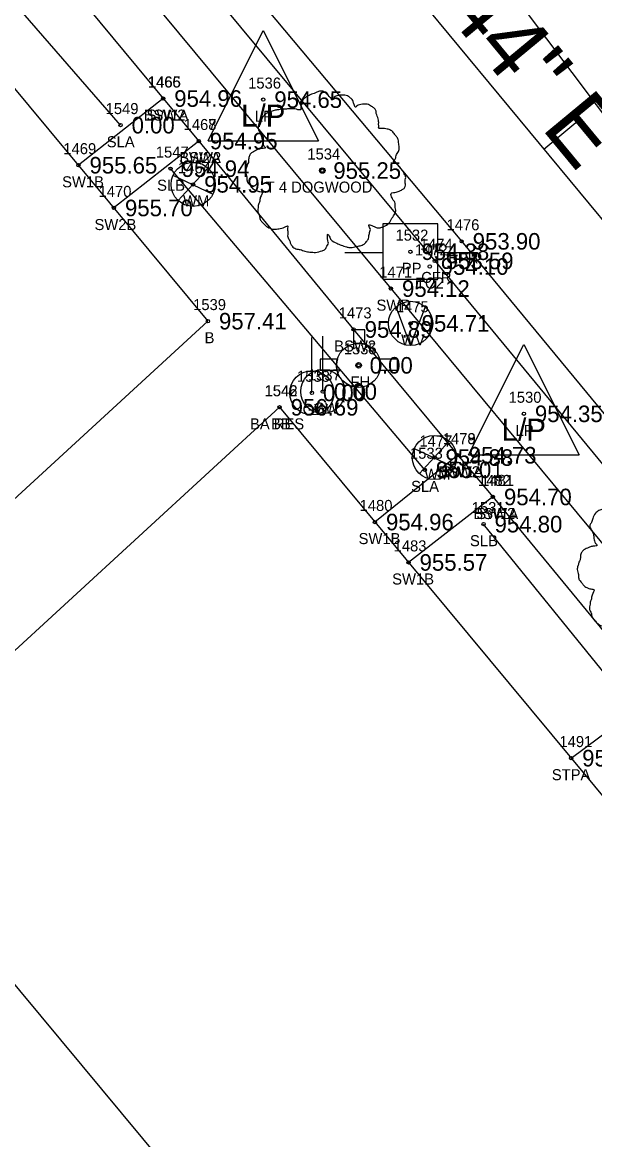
# Model space of a CAD drawing. Extents: x 1575382 to 1578175, y 1099175 to 1101955.
# Drawn here: x 1576458 to 1576509.8, y 1099400.6 to 1099501.7 of the extents above; entities that cross this region are included whole.
import ezdxf

# ---------------------------------------------------------------- set-up
doc = ezdxf.new("R2010")
doc.units = 0
for name, color, linetype in [('RD_EX_Bldg', 7, 'Continuous'), ('RD_EX_Bldg_txCode', 7, 'Continuous'), ('RD_EX_Conc', 7, 'Continuous'), ('RD_EX_Conc_txCode', 7, 'Continuous'), ('RD_EX_Road', 7, 'Continuous'), ('RD_EX_Road_txCode', 7, 'Continuous'), ('RD_EX_TX_Bldg_ELEV', 7, 'Continuous'), ('RD_EX_TX_Conc_ELEV', 7, 'Continuous'), ('RD_EX_TX_Road_ELEV', 7, 'Continuous'), ('RD_EX_TX_UT_ELEV', 7, 'Continuous'), ('RD_EX_TX_VEG_ELEV', 7, 'Continuous'), ('RD_EX_UT', 7, 'Continuous'), ('RD_EX_UT_txCode', 7, 'Continuous'), ('RD_EX_VEG', 7, 'Continuous'), ('RD_EX_VEG_txCode', 7, 'Continuous'), ('RD_HC_Cl', 7, 'Continuous'), ('RD_HC_Data', 7, 'Continuous'), ('RD_HC_Data_Tic', 7, 'Continuous'), ('RD_HC_Survey_ELEV', 7, 'Continuous'), ('RD_SMD_Locator', 7, 'Continuous')]:
    doc.layers.add(name, color=color, linetype=linetype)

msp = doc.modelspace()

# ---------------------------------------------------------------- linework, layer by layer
at = {"layer": 'RD_EX_Bldg'}
for points in [[(1576370.24, 1099519.44), (1576408.46, 1099554.56), (1576474.83, 1099474.68), (1576436.61, 1099439.56), (1576370.24, 1099519.44)], [(1576481.32, 1099466.88), (1576547.69, 1099387), (1576509.46, 1099351.88), (1576443.09, 1099431.76), (1576481.32, 1099466.88)]]:
    msp.add_lwpolyline(points, dxfattribs=at)
at = {"layer": 'RD_EX_Conc'}
for p, q in [((1576470.78, 1099494.84), (1576463.11, 1099488.8)), ((1576474, 1099490.99), (1576466.32, 1099484.93)), ((1576497.44, 1099462.54), (1576489.95, 1099456.49)), ((1576500.63, 1099458.76), (1576492.99, 1099452.83))]:
    msp.add_line(p, q, dxfattribs=at)
for points in [[(1576396.55, 1099574.21), (1576400.94, 1099578.26), (1576405.4, 1099581.45), (1576408.35, 1099582.39), (1576411.1, 1099581.54), (1576412.48, 1099580.16), (1576412.48, 1099580.16), (1576431.43, 1099557.37), (1576462.58, 1099519.63), (1576495.36, 1099480.14), (1576526.3, 1099442.62), (1576558.03, 1099404.43)], [(1576424.53, 1099564.75), (1576421.54, 1099562.11), (1576427.77, 1099554.24), (1576491.4, 1099477.63), (1576522.92, 1099439.59), (1576554.46, 1099401.18)], [(1576417.79, 1099558.83), (1576419.81, 1099556.41), (1576422.78, 1099552.79), (1576443.67, 1099527.67), (1576447.39, 1099523.04), (1576450.38, 1099519.36), (1576454.58, 1099514.36), (1576470.78, 1099494.84), (1576474, 1099490.99), (1576488.02, 1099473.93), (1576497.44, 1099462.54), (1576500.63, 1099458.76), (1576516.67, 1099439.27), (1576520.69, 1099434.46), (1576523.68, 1099430.77), (1576527.93, 1099425.88), (1576541.66, 1099409.22), (1576544.52, 1099405.7), (1576551.21, 1099397.69)], [(1576507.71, 1099435.11), (1576511.48, 1099437.92), (1576525.28, 1099420.93), (1576521.71, 1099418.27)]]:
    msp.add_lwpolyline(points, dxfattribs=at)
at = {"layer": 'RD_EX_Road'}
msp.add_lwpolyline([(1576365.09, 1099547.1), (1576400.46, 1099578.87), (1576404.99, 1099582.28), (1576408.27, 1099583.27), (1576411.47, 1099582.29), (1576413.12, 1099580.85), (1576414.82, 1099582.11), (1576433.7, 1099559), (1576464.95, 1099521.11), (1576497.8, 1099481.91), (1576528.73, 1099444.46), (1576560.01, 1099406.61)], dxfattribs=at)
at = {"layer": 'RD_EX_UT'}
for p, q in [((1576474.84, 1099491.01), (1576479.84, 1099501.01)), ((1576479.84, 1099501.01), (1576484.84, 1099491.01)), ((1576474.84, 1099491.01), (1576484.84, 1099491.01)), ((1576472.14, 1099485.61), (1576474.8, 1099488.51)), ((1576471.65, 1099487.91), (1576475.28, 1099486.19)), ((1576495.65, 1099483.48), (1576490.65, 1099483.48)), ((1576490.65, 1099483.48), (1576490.65, 1099478.48)), ((1576495.65, 1099478.48), (1576495.65, 1099483.48)), ((1576487.22, 1099480.91), (1576490.69, 1099480.91)), ((1576495.58, 1099480.91), (1576499.22, 1099480.91)), ((1576490.65, 1099478.48), (1576495.65, 1099478.48)), ((1576493.18, 1099472.49), (1576491.88, 1099475.97)), ((1576493.18, 1099472.49), (1576494.5, 1099475.93)), ((1576488.02, 1099473.9), (1576488.02, 1099472.62)), ((1576489.02, 1099473.9), (1576488.02, 1099473.9)), ((1576489.02, 1099472.6), (1576489.02, 1099473.9)), ((1576484.24, 1099468.19), (1576484.24, 1099473.19)), ((1576485.23, 1099468.31), (1576485.23, 1099473.31)), ((1576498.43, 1099462.57), (1576503.43, 1099472.57)), ((1576503.43, 1099472.57), (1576508.43, 1099462.57)), ((1576486.56, 1099471.25), (1576485, 1099471.25)), ((1576485, 1099471.25), (1576485, 1099470.25)), ((1576492, 1099471.25), (1576490.39, 1099471.25)), ((1576492, 1099470.25), (1576492, 1099471.25)), ((1576485, 1099470.25), (1576486.52, 1099470.25)), ((1576490.43, 1099470.25), (1576492, 1099470.25)), ((1576493.98, 1099460.87), (1576496.65, 1099463.77)), ((1576493.5, 1099463.16), (1576497.13, 1099461.45)), ((1576498.43, 1099462.57), (1576508.43, 1099462.57))]:
    msp.add_line(p, q, dxfattribs=at)
msp.add_lwpolyline([(1576589.46, 1099388.65), (1576430.6, 1099599.81), (1576417.78, 1099616.34)], dxfattribs=at)
for centre, radius in [((1576473.49, 1099487.07), 2), ((1576493.18, 1099474.48), 2), ((1576488.47, 1099470.68), 2), ((1576488.47, 1099470.68), 0.25), ((1576484.24, 1099468.19), 2), ((1576485.23, 1099468.31), 2), ((1576495.33, 1099462.33), 2)]:
    msp.add_circle(centre, radius, dxfattribs=at)
for start, end in [(74.2455, 103.2128), (163.3387, 192.315), (347.685, 16.6613)]:
    msp.add_arc((1576488.47, 1099470.68), 2, start, end, dxfattribs=at)
at = {"layer": 'RD_EX_VEG'}
for p, q in [((1576466.92, 1099492.43), (1576452.31, 1099509.23)), ((1576494.46, 1099461.22), (1576471.45, 1099488.49)), ((1576514.5, 1099438.14), (1576499.78, 1099456.3))]:
    msp.add_line(p, q, dxfattribs=at)
for centre, radius in [((1576485.18, 1099488.32), 0.25), ((1576485.17, 1099488.3), 0.0001)]:
    msp.add_circle(centre, radius, dxfattribs=at)
for points in [[(1576485.31, 1099495.48), (1576485.01, 1099495.51), (1576484.69, 1099495.41), (1576484.44, 1099495.31), (1576484.21, 1099495.23), (1576483.99, 1099495.13), (1576483.69, 1099494.96), (1576483.46, 1099494.76), (1576483.34, 1099494.51), (1576483.29, 1099494.28), (1576483.24, 1099494.01), (1576483.24, 1099493.83), (1576483.11, 1099493.81), (1576482.96, 1099493.83), (1576482.71, 1099493.91), (1576482.46, 1099493.91), (1576482.21, 1099493.91), (1576481.86, 1099493.88), (1576481.51, 1099493.88), (1576481.24, 1099493.83), (1576480.92, 1099493.78), (1576480.54, 1099493.66), (1576480.19, 1099493.53), (1576479.89, 1099493.28), (1576479.64, 1099492.81), (1576479.52, 1099492.46), (1576479.37, 1099492.21), (1576479.52, 1099491.76), (1576479.69, 1099491.41), (1576479.72, 1099491.21), (1576479.79, 1099490.78), (1576479.89, 1099490.56), (1576480.02, 1099490.36), (1576479.94, 1099490.34), (1576479.57, 1099490.29), (1576479.27, 1099490.19), (1576478.84, 1099489.96), (1576478.62, 1099489.74), (1576478.52, 1099489.41), (1576478.49, 1099489.06), (1576478.39, 1099488.86), (1576478.32, 1099488.59), (1576478.29, 1099488.51), (1576478.24, 1099488.19), (1576478.34, 1099487.74), (1576478.37, 1099487.39), (1576478.49, 1099487.16), (1576478.64, 1099486.99), (1576478.82, 1099486.74), (1576479.22, 1099486.51), (1576479.54, 1099486.41), (1576479.74, 1099486.39), (1576479.57, 1099485.89), (1576479.52, 1099485.54), (1576479.39, 1099485.14), (1576479.39, 1099485.06), (1576479.34, 1099484.59), (1576479.49, 1099484.26), (1576479.57, 1099483.89), (1576479.74, 1099483.66), (1576480.02, 1099483.36), (1576480.34, 1099483.14), (1576480.84, 1099483.01), (1576481.24, 1099483.04), (1576481.81, 1099483.21), (1576482.06, 1099483.29), (1576482.04, 1099483.11), (1576482.06, 1099482.74), (1576482.06, 1099482.31), (1576482.21, 1099481.99), (1576482.31, 1099481.71), (1576482.46, 1099481.46), (1576482.79, 1099481.24), (1576483.19, 1099481.16), (1576483.61, 1099481.01), (1576484.06, 1099480.94), (1576484.56, 1099480.91), (1576485.16, 1099481.06), (1576485.44, 1099481.19), (1576485.54, 1099481.36), (1576485.74, 1099481.74), (1576485.69, 1099481.96), (1576485.71, 1099482.56), (1576485.81, 1099482.39), (1576485.99, 1099482.04), (1576486.49, 1099481.74), (1576486.89, 1099481.56), (1576487.36, 1099481.41), (1576487.66, 1099481.34), (1576488.14, 1099481.41), (1576488.51, 1099481.49), (1576488.89, 1099481.61), (1576489.19, 1099481.89), (1576489.36, 1099482.16), (1576489.41, 1099482.44), (1576489.49, 1099482.81), (1576489.54, 1099482.99)], [(1576489.54, 1099482.99), (1576489.46, 1099483.16), (1576489.41, 1099483.41), (1576489.49, 1099483.39), (1576489.66, 1099483.34), (1576489.94, 1099483.21), (1576490.16, 1099483.14), (1576490.49, 1099483.16), (1576490.76, 1099483.26), (1576491.21, 1099483.54), (1576491.49, 1099484.01), (1576491.76, 1099484.41), (1576491.84, 1099484.74), (1576491.79, 1099484.96), (1576491.76, 1099485.46), (1576491.56, 1099485.71), (1576491.51, 1099485.84), (1576491.41, 1099486.24), (1576491.49, 1099486.29), (1576491.76, 1099486.34), (1576492.14, 1099486.46), (1576492.41, 1099486.59), (1576492.63, 1099486.76), (1576492.71, 1099486.99), (1576492.68, 1099487.39), (1576492.73, 1099487.79), (1576492.66, 1099487.94), (1576492.56, 1099488.09), (1576492.48, 1099488.29), (1576492.34, 1099488.44), (1576492.24, 1099488.59), (1576492.14, 1099488.69), (1576492.01, 1099488.84), (1576491.84, 1099488.96), (1576491.69, 1099489.01), (1576491.64, 1099489.16), (1576491.79, 1099489.36), (1576491.84, 1099489.46), (1576491.86, 1099489.69), (1576492.09, 1099490.04), (1576492.14, 1099490.43), (1576492.09, 1099490.86), (1576492.04, 1099491.13), (1576491.89, 1099491.41), (1576491.69, 1099491.66), (1576491.56, 1099491.83), (1576491.39, 1099491.96), (1576491.06, 1099492.08), (1576490.81, 1099492.13), (1576490.46, 1099492.13), (1576490.26, 1099492.18), (1576490.29, 1099492.23), (1576490.29, 1099492.38), (1576490.29, 1099492.66), (1576490.21, 1099493.11), (1576490.06, 1099493.61), (1576490.06, 1099493.63), (1576489.96, 1099493.88), (1576489.74, 1099494.08), (1576489.56, 1099494.18), (1576489.36, 1099494.31), (1576489.11, 1099494.33), (1576488.81, 1099494.33), (1576488.54, 1099494.28), (1576488.34, 1099494.18), (1576488.16, 1099494.06), (1576488.09, 1099494.21), (1576487.99, 1099494.51), (1576487.94, 1099494.66), (1576487.79, 1099494.83), (1576487.56, 1099495.03), (1576487.11, 1099495.16), (1576486.49, 1099495.08), (1576486.19, 1099494.88), (1576486.04, 1099494.71), (1576485.99, 1099494.83), (1576485.79, 1099495.03), (1576485.69, 1099495.21), (1576485.51, 1099495.33), (1576485.36, 1099495.43), (1576485.26, 1099495.48)], [(1576515.34, 1099459.48), (1576515.04, 1099459.5), (1576514.72, 1099459.4), (1576514.47, 1099459.3), (1576514.24, 1099459.23), (1576514.02, 1099459.13), (1576513.72, 1099458.95), (1576513.5, 1099458.75), (1576513.37, 1099458.5), (1576513.32, 1099458.28), (1576513.27, 1099458), (1576513.27, 1099457.83), (1576513.15, 1099457.8), (1576513, 1099457.83), (1576512.75, 1099457.9), (1576512.5, 1099457.9), (1576512.25, 1099457.9), (1576511.9, 1099457.88), (1576511.55, 1099457.88), (1576511.27, 1099457.83), (1576510.95, 1099457.78), (1576510.57, 1099457.65), (1576510.22, 1099457.53), (1576509.92, 1099457.28), (1576509.67, 1099456.8), (1576509.55, 1099456.45), (1576509.4, 1099456.2), (1576509.55, 1099455.75), (1576509.72, 1099455.4), (1576509.75, 1099455.2), (1576509.82, 1099454.78), (1576509.92, 1099454.56), (1576510.05, 1099454.36), (1576509.97, 1099454.33), (1576509.6, 1099454.28), (1576509.3, 1099454.18), (1576508.87, 1099453.96), (1576508.65, 1099453.73), (1576508.55, 1099453.41), (1576508.52, 1099453.06), (1576508.42, 1099452.86), (1576508.35, 1099452.58), (1576508.32, 1099452.51), (1576508.27, 1099452.18), (1576508.37, 1099451.73), (1576508.4, 1099451.38), (1576508.52, 1099451.16), (1576508.67, 1099450.98), (1576508.85, 1099450.73), (1576509.25, 1099450.51), (1576509.57, 1099450.41), (1576509.77, 1099450.38), (1576509.6, 1099449.88), (1576509.55, 1099449.53), (1576509.42, 1099449.13), (1576509.42, 1099449.06), (1576509.37, 1099448.58), (1576509.52, 1099448.26), (1576509.6, 1099447.88), (1576509.77, 1099447.66), (1576510.05, 1099447.36), (1576510.37, 1099447.13), (1576510.87, 1099447.01), (1576511.27, 1099447.03), (1576511.85, 1099447.21), (1576512.1, 1099447.28), (1576512.07, 1099447.11), (1576512.1, 1099446.73), (1576512.1, 1099446.31), (1576512.25, 1099445.98), (1576512.35, 1099445.71), (1576512.5, 1099445.46), (1576512.82, 1099445.23), (1576513.22, 1099445.16), (1576513.65, 1099445.01), (1576514.09, 1099444.93), (1576514.59, 1099444.91), (1576515.19, 1099445.06), (1576515.47, 1099445.18), (1576515.57, 1099445.36), (1576515.77, 1099445.73), (1576515.72, 1099445.96), (1576515.74, 1099446.56), (1576515.84, 1099446.38), (1576516.02, 1099446.03), (1576516.52, 1099445.73), (1576516.92, 1099445.56), (1576517.39, 1099445.41), (1576517.69, 1099445.33), (1576518.17, 1099445.41), (1576518.54, 1099445.48), (1576518.92, 1099445.61), (1576519.22, 1099445.88), (1576519.39, 1099446.16), (1576519.44, 1099446.43), (1576519.52, 1099446.81), (1576519.57, 1099446.98)]]:
    msp.add_spline(points, degree=3, dxfattribs=at)
at = {"layer": 'RD_HC_Cl'}
msp.add_line((1576414.59, 1099599.72), (1576569.26, 1099412.94), dxfattribs=at)
at = {"layer": 'RD_HC_Data_Tic'}
msp.add_line((1576505.23, 1099490.26), (1576508.31, 1099492.81), dxfattribs=at)
at = {"layer": 'RD_SMD_Locator'}
for centre in [(1576470.78, 1099494.84), (1576470.78, 1099494.84), (1576479.84, 1099494.74), (1576466.92, 1099492.43), (1576474, 1099490.99), (1576474, 1099490.99), (1576463.11, 1099488.8), (1576471.45, 1099488.49), (1576485.18, 1099488.32), (1576473.49, 1099487.07), (1576466.32, 1099484.93), (1576497.8, 1099481.91), (1576493.16, 1099480.97), (1576495.36, 1099480.14), (1576494.91, 1099479.63), (1576491.4, 1099477.63), (1576474.83, 1099474.68), (1576488.02, 1099473.93), (1576493.18, 1099474.48), (1576488.47, 1099470.68), (1576484.24, 1099468.19), (1576485.23, 1099468.31), (1576481.32, 1099466.88), (1576481.32, 1099466.88), (1576503.43, 1099466.29), (1576497.44, 1099462.54), (1576497.44, 1099462.54), (1576495.33, 1099462.33), (1576494.46, 1099461.22), (1576500.63, 1099458.76), (1576500.63, 1099458.76), (1576489.95, 1099456.49), (1576499.78, 1099456.3), (1576492.99, 1099452.83), (1576507.71, 1099435.11)]:
    msp.add_circle(centre, 0.15, dxfattribs=at)

# ---------------------------------------------------------------- texts
at = {"layer": 'RD_EX_Bldg_txCode'}
for s, p in [('1539', (1576473.49, 1099475.68)), ('B', (1576474.53, 1099472.68)), ('1546', (1576479.95, 1099467.88)), ('1542', (1576479.97, 1099467.88)), ('BA RES', (1576478.64, 1099464.88)), ('BB', (1576480.54, 1099464.88))]:
    msp.add_text(s, height=1, dxfattribs=at).set_placement(p)
at = {"layer": 'RD_EX_Conc_txCode'}
for s, p in [('1466', (1576469.38, 1099495.84)), ('1465', (1576469.41, 1099495.84)), ('BSW2', (1576469.01, 1099492.84)), ('SW1A', (1576469.28, 1099492.84)), ('1467', (1576472.63, 1099491.99)), ('1468', (1576472.63, 1099491.99)), ('1469', (1576461.74, 1099489.8)), ('SW2A', (1576472.22, 1099488.99)), ('BSW2', (1576472.24, 1099488.99)), ('SW1B', (1576461.63, 1099486.8)), ('1470', (1576464.93, 1099485.93)), ('SW2B', (1576464.56, 1099482.93)), ('1474', (1576494.01, 1099481.14)), ('1472', (1576493.56, 1099480.63)), ('1471', (1576490.34, 1099478.63)), ('CFR', (1576494.13, 1099478.14)), ('TC2', (1576493.66, 1099477.63)), ('1473', (1576486.67, 1099474.93)), ('SWR', (1576490.09, 1099475.63)), ('BSW2', (1576486.26, 1099471.93)), ('1478', (1576496.09, 1099463.54)), ('1479', (1576496.09, 1099463.54)), ('BSW2', (1576495.67, 1099460.54)), ('SW1A', (1576495.94, 1099460.54)), ('1482', (1576499.28, 1099459.76)), ('1481', (1576499.56, 1099459.76)), ('1480', (1576488.56, 1099457.49)), ('BSW2', (1576498.86, 1099456.76)), ('SW1A', (1576499.13, 1099456.76)), ('SW1B', (1576488.47, 1099454.49)), ('1483', (1576491.64, 1099453.83)), ('SW1B', (1576491.51, 1099450.83)), ('1491', (1576506.65, 1099436.11)), ('STPA', (1576505.96, 1099433.11))]:
    msp.add_text(s, height=1, dxfattribs=at).set_placement(p)
at = {"layer": 'RD_EX_Road_txCode'}
for s, p in [('1476', (1576496.43, 1099482.91)), ('EPR', (1576496.57, 1099479.91))]:
    msp.add_text(s, height=1, dxfattribs=at).set_placement(p)
at = {"layer": 'RD_EX_TX_Bldg_ELEV'}
for s, p in [('957.41', (1576475.83, 1099473.93)), ('956.69', (1576482.32, 1099466.13)), ('956.69', (1576482.32, 1099466.13))]:
    msp.add_text(s, height=1.5, dxfattribs=at).set_placement(p)
at = {"layer": 'RD_EX_TX_Conc_ELEV'}
for s, p in [('954.96', (1576471.78, 1099494.09)), ('954.96', (1576471.78, 1099494.09)), ('954.95', (1576475, 1099490.24)), ('954.95', (1576475, 1099490.24)), ('955.65', (1576464.11, 1099488.05)), ('955.70', (1576467.32, 1099484.18)), ('953.59', (1576496.36, 1099479.39)), ('954.10', (1576495.91, 1099478.88)), ('954.12', (1576492.4, 1099476.88)), ('954.89', (1576489.02, 1099473.18)), ('954.73', (1576498.44, 1099461.79)), ('954.73', (1576498.44, 1099461.79)), ('954.70', (1576501.63, 1099458.01)), ('954.70', (1576501.63, 1099458.01)), ('954.96', (1576490.95, 1099455.74)), ('955.57', (1576493.99, 1099452.08)), ('955.61', (1576508.71, 1099434.36))]:
    msp.add_text(s, height=1.5, dxfattribs=at).set_placement(p)
at = {"layer": 'RD_EX_TX_Road_ELEV'}
msp.add_text('953.90', height=1.5, dxfattribs=at).set_placement((1576498.8, 1099481.16))
at = {"layer": 'RD_EX_TX_UT_ELEV'}
for s, p in [('954.65', (1576480.84, 1099493.99)), ('954.95', (1576474.49, 1099486.32)), ('954.71', (1576494.18, 1099473.73)), ('0.00', (1576489.47, 1099469.93)), ('0.00', (1576485.24, 1099467.44)), ('0.00', (1576486.23, 1099467.56)), ('954.35', (1576504.43, 1099465.54)), ('954.88', (1576496.33, 1099461.58))]:
    msp.add_text(s, height=1.5, dxfattribs=at).set_placement(p)
at = {"layer": 'RD_EX_TX_VEG_ELEV'}
for s, p in [('0.00', (1576467.92, 1099491.68)), ('954.94', (1576472.45, 1099487.74)), ('955.25', (1576486.18, 1099487.57)), ('955.01', (1576495.46, 1099460.47)), ('954.80', (1576500.78, 1099455.55))]:
    msp.add_text(s, height=1.5, dxfattribs=at).set_placement(p)
at = {"layer": 'RD_EX_UT'}
for p in [(1576477.83, 1099492.3), (1576501.42, 1099463.85)]:
    msp.add_text('L/P', height=2, dxfattribs=at).set_placement(p)
at = {"layer": 'RD_EX_UT_txCode'}
for s, p in [('1536', (1576478.47, 1099495.74)), ('LP', (1576479.08, 1099492.74)), ('1464', (1576472.12, 1099488.07)), ('WM', (1576472.58, 1099485.07)), ('1532', (1576491.81, 1099481.97)), ('PP', (1576492.38, 1099478.97)), ('1475', (1576491.84, 1099475.48)), ('WV', (1576492.32, 1099472.48)), ('1535', (1576487.13, 1099471.68)), ('1538', (1576482.89, 1099469.19)), ('1537', (1576483.88, 1099469.31)), ('FH', (1576487.74, 1099468.68)), ('1530', (1576502.05, 1099467.29)), ('GW', (1576483.4, 1099466.19)), ('GW', (1576484.39, 1099466.31)), ('LP', (1576502.68, 1099464.29)), ('1477', (1576493.98, 1099463.33)), ('WM', (1576494.42, 1099460.33))]:
    msp.add_text(s, height=1, dxfattribs=at).set_placement(p)
at = {"layer": 'RD_EX_VEG_txCode'}
for s, p in [('1549', (1576465.57, 1099493.43)), ('SLA', (1576465.67, 1099490.43)), ('1547', (1576470.11, 1099489.49)), ('1534', (1576483.83, 1099489.32)), ('SLB', (1576470.23, 1099486.49)), ('T 4 DOGWOOD', (1576480.06, 1099486.32)), ('1533', (1576493.12, 1099462.22)), ('SLA', (1576493.22, 1099459.22)), ('1531', (1576498.71, 1099457.3)), ('SLB', (1576498.55, 1099454.3))]:
    msp.add_text(s, height=1, dxfattribs=at).set_placement(p)
at = {"layer": 'RD_HC_Data'}
msp.add_text('S 39%%d 37\' 44" E', height=6, rotation=309.6288, dxfattribs=at).set_placement((1576473.91, 1099529.66))
at = {"layer": 'RD_HC_Survey_ELEV'}
msp.add_text('954.38', height=1.5, dxfattribs=at).set_placement((1576494.16, 1099480.22))

doc.saveas('drawing.dxf')
